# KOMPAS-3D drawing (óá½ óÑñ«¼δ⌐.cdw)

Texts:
  ПЛК.715413.01
  Вал тихоходный
  Noncommercial version
  1. Термообработка HB190...210 - улучшение, кроме места
  указанного особо.
  2. * Размер обеспечить инструментом.
  3. Острые кромки притупить фаской 1,6Х45
  4. Неуказанные предельные отклонения размеров: отверстий Н14,
  валов h14, остальное   0.5IT14
  @Arial Unicode MS
  Ra 6.3
  полировать
  ТВЧ.HRC 48...53 h0,9...1,1
  Ra1.6
  Ra0.8
  Symbol
  R0.4max
  ACAD_ISO08W100_RGB_255_128_0_SC_0.25_THICK_0.15
  POLYLINE_STYLE_0.18_RGB_0_0_255
  gost6_RGB_255_128_0_SC_1_THICK_0.15
  ACAD_ISO10W100_RGB_255_128_0_SC_0.5_THICK_0.15
  ACAD_ISO10W100_RGB_255_128_0_SC_0.75_THICK_0.15
  ACAD_ISO10W100_RGB_255_128_0_SC_1_THICK_0.15
  ACAD_ISO10W100_RGB_255_63_0_SC_0.5_THICK_0.15
  ACAD_ISO10W100_RGB_255_63_0_SC_1_THICK_0.15
  Стили документа
  Сталь 45 ГОСТ 1050-88
  ПЛК.РЦО.180.00.02-
  Вавилин В.В
Dimensions and other numbers on the sheet: 0.03; 0.025; 0,4; 0.01; 0,25; 3; 70; 65; 10; 9; 90; 5; 97; 78; 38; 110; 130; 39; 491; 75; 67,5; 20; 0.06; 59; 18; 0.05; 0.02; 1:1; 1; 0; 2; 4; 6; 7; 8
